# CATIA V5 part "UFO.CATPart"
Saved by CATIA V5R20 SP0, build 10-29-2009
Part number: 零件1
Bounding box of the stored display mesh (mm): x -225 to 225, y -225 to 224.989, z 110 to 190
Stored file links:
  C:\Users\16057\Documents\180511420 创意设计\UFO.CATPart
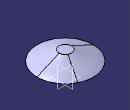
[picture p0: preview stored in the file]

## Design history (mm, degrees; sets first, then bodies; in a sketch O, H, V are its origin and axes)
Body1 (main body)
  Plane1: stored without definition
  Plane2: type Offset, RefPlane Plane1, Offset 20
  Plane3: type Offset, RefPlane Plane2, Offset 20
  Plane4: type Offset, RefPlane Plane3, Offset 20
  Plane5: type Offset, RefPlane Plane4, Offset 20
  Plane6: type Offset, RefPlane Plane5, Offset 20
  DatumCurve1
  Sketch1 on Plane5, origin (0, 0, 190), H (1, 0, 0), V (0, 1, 0)
    circle A1 centre (0, 0) radius 50
  Sketch2 on Plane4, origin (0, 0, 170), H (1, 0, 0), V (0, 1, 0)
    circle A1 centre (0, 0) radius 92.1954
  Sketch3 on Plane3, origin (0, 0, 150), H (1, 0, 0), V (0, 1, 0)
    circle A1 centre (0, 0) radius 138.9244
  Sketch4 on Plane2, origin (0, 0, 130), H (1, 0, 0), V (0, 1, 0)
    circle A1 centre (0, 0) radius 186.0108
  Loft1: solid, Sections (Sketch1; Sketch2; Sketch3; Sketch4; DatumCurve1)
